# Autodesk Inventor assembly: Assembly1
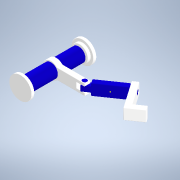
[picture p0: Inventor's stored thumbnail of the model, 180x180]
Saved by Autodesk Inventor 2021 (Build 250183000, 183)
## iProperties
Created: 2025-05
Part Number: Assembly1
Document SubType Name: Assembly
Designer: Aaditya
Author: Aaditya
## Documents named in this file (6)
- D:\Autodesk Files\Assembly1.iam
- D:\Autodesk Files\Part1a.ipt
- D:\Autodesk Files\Part1b.ipt
- D:\Autodesk Files\Part2.ipt
- D:\Autodesk Files\Part3.ipt
- D:\Autodesk Files\Part4.ipt
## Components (5 placed, 5 different names)
1. Part1a:1 — Cylindrical:1
2. Part1b:1 — Cylindrical:1, Rotational:1
3. Part2:1 — Rotational:1, Rotational:2
4. Part3:1 — Rotational:2, Rotational:3
5. Part4:1 — Rotational:3
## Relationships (4: RevoluteJoint 3, CylindricalJoint 1)
- Cylindrical:1: Part1a:1 ↔ Part1b:1
- Rotational:1 [RevoluteJoint]: Part1b:1 ↔ Part2:1
- Rotational:2 [RevoluteJoint]: Part2:1 ↔ Part3:1
- Rotational:3 [RevoluteJoint]: Part3:1 ↔ Part4:1
